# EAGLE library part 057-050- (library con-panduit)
CONNECTOR 50-pin series 057 contact pc board low profile headers
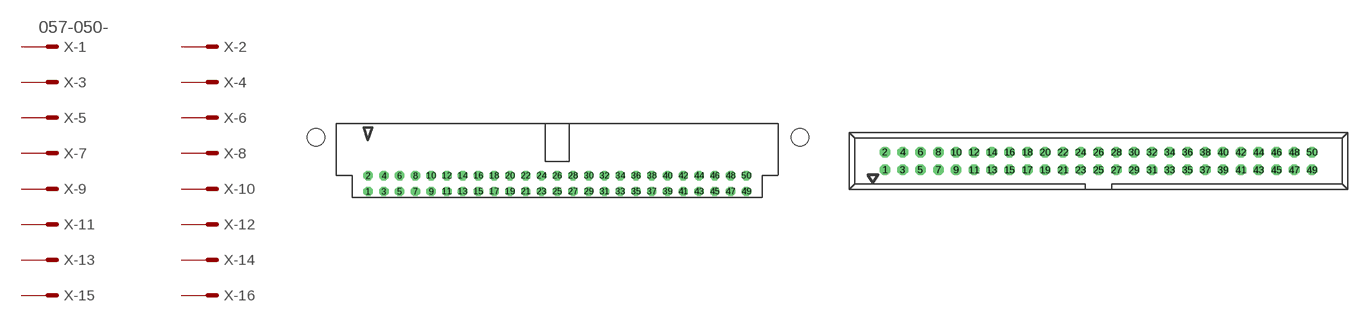
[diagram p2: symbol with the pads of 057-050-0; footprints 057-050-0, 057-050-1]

Designator prefix X; gates -1=MV -2=M -3=M -4=M -5=M -6=M -7=M -8=M -9=M -10=M -11=M -12=M -13=M -14=M -15=M -16=M -17=M -18=M -19=M -20=M -21=M -22=M -23=M -24=M -25=M -26=M -27=M -28=M -29=M -30=M -31=M -32=M -33=M -34=M -35=M -36=M -37=M -38=M -39=M -40=M -41=M -42=M -43=M -44=M -45=M -46=M -47=M -48=M -49=M -50=M

## 057-050-0 (OC_FARNELL: unknown; OC_NEWARK: unknown)  [057-050-0]
1  -1:S  pas
2  -2:S  pas
3  -3:S  pas
4  -4:S  pas
5  -5:S  pas
6  -6:S  pas
7  -7:S  pas
8  -8:S  pas
9  -9:S  pas
10  -10:S  pas
11  -11:S  pas
12  -12:S  pas
13  -13:S  pas
14  -14:S  pas
15  -15:S  pas
16  -16:S  pas
17  -17:S  pas
18  -18:S  pas
19  -19:S  pas
20  -20:S  pas
21  -21:S  pas
22  -22:S  pas
23  -23:S  pas
24  -24:S  pas
25  -25:S  pas
26  -26:S  pas
27  -27:S  pas
28  -28:S  pas
29  -29:S  pas
30  -30:S  pas
31  -31:S  pas
32  -32:S  pas
33  -33:S  pas
34  -34:S  pas
35  -35:S  pas
36  -36:S  pas
37  -37:S  pas
38  -38:S  pas
39  -39:S  pas
40  -40:S  pas
41  -41:S  pas
42  -42:S  pas
43  -43:S  pas
44  -44:S  pas
45  -45:S  pas
46  -46:S  pas
47  -47:S  pas
48  -48:S  pas
49  -49:S  pas
50  -50:S  pas

## 057-050-1 (OC_FARNELL: unknown; OC_NEWARK: unknown)  [057-050-1]
Pads as for 057-050-0

## Footprint 057-050-0 (pad centres in mm)
CONNECTOR series 057 contact pc board low profile headers angled
drill 1 octagon: 1 -30.48,-5.08; 2 -30.48,-2.54; 3 -27.94,-5.08; 4 -27.94,-2.54; 5 -25.4,-5.08; 6 -25.4,-2.54; 7 -22.86,-5.08; 8 -22.86,-2.54; 9 -20.32,-5.08; 10 -20.32,-2.54; 11 -17.78,-5.08; 12 -17.78,-2.54; 13 -15.24,-5.08; 14 -15.24,-2.54; 15 -12.7,-5.08; 16 -12.7,-2.54; 17 -10.16,-5.08; 18 -10.16,-2.54; 19 -7.62,-5.08; 20 -7.62,-2.54; 21 -5.08,-5.08; 22 -5.08,-2.54; 23 -2.54,-5.08; 24 -2.54,-2.54; 25 0,-5.08; 26 0,-2.54; 27 2.54,-5.08; 28 2.54,-2.54; 29 5.08,-5.08; 30 5.08,-2.54; 31 7.62,-5.08; 32 7.62,-2.54; 33 10.16,-5.08; 34 10.16,-2.54; 35 12.7,-5.08; 36 12.7,-2.54; 37 15.24,-5.08; 38 15.24,-2.54; 39 17.78,-5.08; 40 17.78,-2.54; 41 20.32,-5.08; 42 20.32,-2.54; 43 22.86,-5.08; 44 22.86,-2.54; 45 25.4,-5.08; 46 25.4,-2.54; 47 27.94,-5.08; 48 27.94,-2.54; 49 30.48,-5.08; 50 30.48,-2.54
hole 2.8 at -38.88,3.66
hole 2.8 at 39.13,3.66

## Footprint 057-050-1 (pad centres in mm)
CONNECTOR series 057 contact pc board low profile headers straight
drill 1 octagon: 1 -30.48,-1.27; 2 -30.48,1.27; 3 -27.94,-1.27; 4 -27.94,1.27; 5 -25.4,-1.27; 6 -25.4,1.27; 7 -22.86,-1.27; 8 -22.86,1.27; 9 -20.32,-1.27; 10 -20.32,1.27; 11 -17.78,-1.27; 12 -17.78,1.27; 13 -15.24,-1.27; 14 -15.24,1.27; 15 -12.7,-1.27; 16 -12.7,1.27; 17 -10.16,-1.27; 18 -10.16,1.27; 19 -7.62,-1.27; 20 -7.62,1.27; 21 -5.08,-1.27; 22 -5.08,1.27; 23 -2.54,-1.27; 24 -2.54,1.27; 25 0,-1.27; 26 0,1.27; 27 2.54,-1.27; 28 2.54,1.27; 29 5.08,-1.27; 30 5.08,1.27; 31 7.62,-1.27; 32 7.62,1.27; 33 10.16,-1.27; 34 10.16,1.27; 35 12.7,-1.27; 36 12.7,1.27; 37 15.24,-1.27; 38 15.24,1.27; 39 17.78,-1.27; 40 17.78,1.27; 41 20.32,-1.27; 42 20.32,1.27; 43 22.86,-1.27; 44 22.86,1.27; 45 25.4,-1.27; 46 25.4,1.27; 47 27.94,-1.27; 48 27.94,1.27; 49 30.48,-1.27; 50 30.48,1.27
